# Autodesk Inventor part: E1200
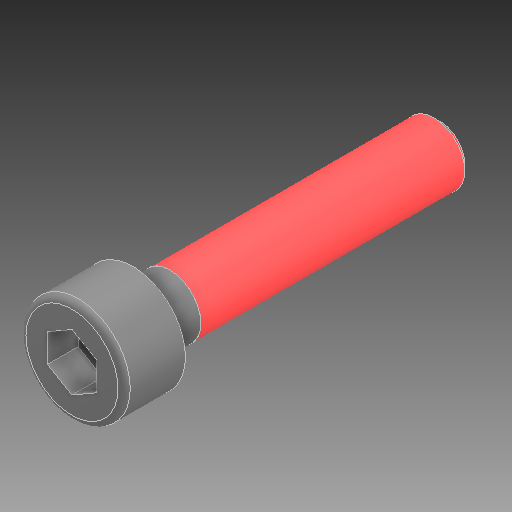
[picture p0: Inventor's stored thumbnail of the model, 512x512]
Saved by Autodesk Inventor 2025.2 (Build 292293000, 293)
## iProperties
Created: 2025-03
Part Number: E1200
Material: Všeobecné
Document SubType Name: Modeling
Designer: Patrik
Density: 1 g/cm^3
Appearance: Výchozí
Stock Number: E 31621_52_30_63
Mass: 0.73741 g
Surface Area: 6.62537 cm^2
Volume: 0.73741 cm^3
Author: Patrik
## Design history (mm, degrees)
feature "Base1"
node "Těleso1"
